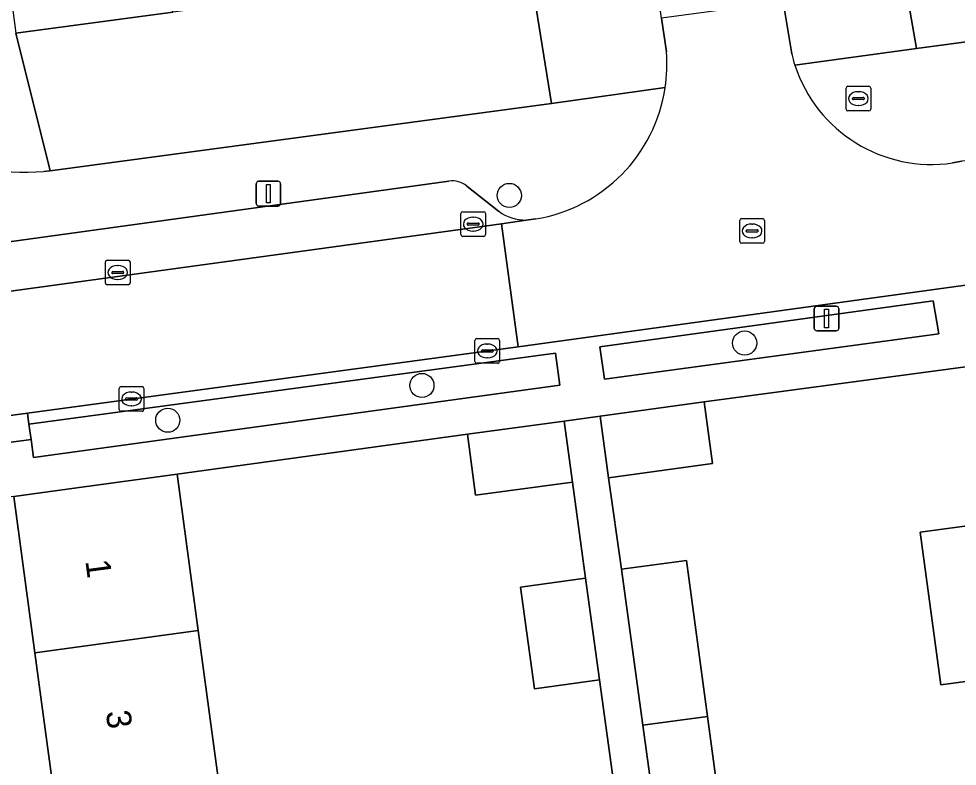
# Model space of a CAD drawing. Extents: x 159053 to 160042, y 380449 to 381423.
# Drawn here: x 159553.7 to 159591.74, y 380955.93 to 380986.2 of the extents above; entities that cross this region are included whole.
import ezdxf

# ---------------------------------------------------------------- set-up
doc = ezdxf.new("R2010")
doc.units = 0
for name, color, linetype in [('IMGEO_Boom', 7, 'Continuous'), ('IMGEO_Brandkraan', 7, 'Continuous'), ('IMGEO_Erf', 7, 'Continuous'), ('IMGEO_Groenvoorziening', 7, 'Continuous'), ('IMGEO_Kolk', 7, 'Continuous'), ('IMGEO_Lichtmast', 7, 'Continuous'), ('IMGEO_Muur', 7, 'Continuous'), ('IMGEO_Pand', 7, 'Continuous'), ('IMGEO_Pand_nummerreeks', 7, 'Continuous'), ('IMGEO_Parkeervlak_open', 7, 'Continuous'), ('IMGEO_Rijbaan_lokaal_open', 7, 'Continuous'), ('IMGEO_Rioolput', 7, 'Continuous'), ('IMGEO_Voetpad_op_trap', 7, 'Continuous'), ('IMGEO_Voetpad_open', 7, 'Continuous')]:
    doc.layers.add(name, color=color, linetype=linetype)

msp = doc.modelspace()

# ---------------------------------------------------------------- linework, layer by layer
at = {"layer": 'IMGEO_Boom'}
for centre in [(159573.584, 380979.049), (159583.121, 380973.071), (159570.042, 380971.353), (159559.743, 380969.946)]:
    msp.add_circle(centre, 0.489, dxfattribs=at)
at = {"layer": 'IMGEO_Brandkraan'}
for p, q in [((159587.23, 380982.545), (159587.23, 380983.397)), ((159587.305, 380983.471), (159588.157, 380983.471)), ((159587.718, 380983.251), (159587.743, 380983.251)), ((159588.231, 380983.397), (159588.231, 380982.545)), ((159587.489, 380982.965), (159587.489, 380982.977)), ((159587.927, 380982.928), (159587.529, 380982.928)), ((159587.532, 380983.014), (159587.93, 380983.014)), ((159587.973, 380982.977), (159587.973, 380982.965)), ((159588.157, 380982.471), (159587.305, 380982.471)), ((159587.741, 380982.691), (159587.716, 380982.691))]:
    msp.add_line(p, q, dxfattribs=at)
for points in [[(159587.23, 380982.545), (159587.23, 380983.397)], [(159587.305, 380983.471), (159588.157, 380983.471)], [(159588.231, 380983.397), (159588.231, 380982.545)], [(159588.157, 380982.471), (159587.305, 380982.471)]]:
    msp.add_lwpolyline(points, dxfattribs=at)
for centre, radius, start, end in [((159587.307, 380983.395), 0.0765, 91.552, 178.448), ((159587.307, 380983.395), 0.0765, 91.552, 178.448), ((159588.155, 380983.395), 0.0765, 1.552, 88.448), ((159588.155, 380983.395), 0.0765, 1.552, 88.448), ((159587.529, 380982.974), 0.0403, 85.8775, 175.7526), ((159587.526, 380982.964), 0.0366, 178.938, 274.7102), ((159587.93, 380982.971), 0.043, 264.8664, 352.4533), ((159587.934, 380982.976), 0.0386, 1.7309, 96.639), ((159587.307, 380982.547), 0.0765, 181.552, 268.448), ((159587.307, 380982.547), 0.0765, 181.552, 268.448), ((159588.155, 380982.547), 0.0765, 271.552, 358.448), ((159588.155, 380982.547), 0.0765, 271.552, 358.448)]:
    msp.add_arc(centre, radius, start, end, dxfattribs=at)
for centre, major_axis, ratio, start_param, end_param in [((159587.717, 380982.971), (-0.387, 0.002), 0.722429, 4.712389, 7.853982), ((159587.742, 380982.971), (-0.39, 0.002), 0.717154, 1.570796, 4.712389)]:
    msp.add_ellipse(centre, major_axis=major_axis, ratio=ratio, start_param=start_param, end_param=end_param, dxfattribs=at)
at = {"layer": 'IMGEO_Erf'}
msp.add_lwpolyline([(159629.325, 381012.778), (159620.225, 381011.443), (159619.631, 381015.49), (159606.715, 381013.595), (159606.672, 381013.887), (159603.856, 381013.811), (159603.9, 381013.367), (159601.077, 381012.94), (159595.844, 381012.15), (159595.511, 381014.617), (159594.439, 381014.46), (159594.956, 381010.935), (159586.122, 381009.639), (159587.893, 380997.568), (159590.084, 380985.004), (159632.613, 380990.715), (159631.088, 381000), (159630.309, 381005.645)], close=True, dxfattribs=at)
for points in [[(159552.695, 380992.276), (159559.053, 380993.13), (159565.262, 380993.963), (159566.666, 380994.152), (159571.621, 380994.818), (159572.515, 380988.162), (159566.157, 380987.308), (159559.948, 380986.474), (159553.589, 380985.62), (159554.983, 380980.049), (159575.287, 380982.768), (159574.532, 380987.48), (159573.254, 380997.153), (159571.578, 381009.42), (159563.123, 381008.171), (159562.595, 381011.752), (159561.106, 381011.532), (159561.428, 381009.12), (159556.975, 381008.526), (159553.35, 381008.042)], [(159593.088, 380972.249), (159581.476, 380970.686), (159581.814, 380968.189), (159577.607, 380967.619), (159578.129, 380963.91), (159580.762, 380964.266), (159581.616, 380957.945), (159582.173, 380953.826)], [(159577.808, 380955.319), (159577.242, 380959.429), (159574.599, 380959.064), (159574.032, 380963.18), (159576.675, 380963.544), (159576.138, 380967.442), (159572.22, 380966.911), (159571.886, 380969.384), (159560.123, 380967.756), (159560.979, 380961.426), (159561.815, 380955.248)], [(159594.782, 380959.727), (159591.065, 380959.224), (159590.229, 380965.41), (159593.945, 380965.913)]]:
    msp.add_lwpolyline(points, dxfattribs=at)
at = {"layer": 'IMGEO_Groenvoorziening'}
msp.add_lwpolyline([(159554.723, 380980.014), (159554.983, 380980.049), (159553.589, 380985.62)], dxfattribs=at)
for points in [[(159590.984, 380973.45), (159590.756, 380974.787), (159577.253, 380972.921), (159577.439, 380971.615)], [(159575.629, 380971.369), (159575.461, 380972.664), (159554.113, 380969.784), (159554.204, 380969.164), (159554.307, 380968.431)]]:
    msp.add_lwpolyline(points, close=True, dxfattribs=at)
msp.add_arc((159553.913, 380997.773), 17.777, 239.325, 272.6107, dxfattribs=at)
at = {"layer": 'IMGEO_Kolk'}
for p, q in [((159571.621, 380977.462), (159571.621, 380978.314)), ((159571.696, 380978.388), (159572.548, 380978.388)), ((159572.622, 380978.314), (159572.622, 380977.462)), ((159571.88, 380977.882), (159571.88, 380977.894)), ((159572.318, 380977.845), (159571.92, 380977.845)), ((159571.923, 380977.931), (159572.321, 380977.931)), ((159572.109, 380978.168), (159572.134, 380978.168)), ((159572.364, 380977.894), (159572.364, 380977.882)), ((159572.132, 380977.608), (159572.107, 380977.608)), ((159572.548, 380977.388), (159571.696, 380977.388)), ((159557.214, 380975.502), (159557.214, 380976.354)), ((159557.289, 380976.428), (159558.141, 380976.428)), ((159558.215, 380976.354), (159558.215, 380975.502)), ((159557.473, 380975.922), (159557.473, 380975.934)), ((159557.516, 380975.971), (159557.914, 380975.971)), ((159557.702, 380976.208), (159557.727, 380976.208)), ((159557.957, 380975.934), (159557.957, 380975.922)), ((159557.911, 380975.885), (159557.513, 380975.885)), ((159557.725, 380975.648), (159557.7, 380975.648)), ((159558.141, 380975.428), (159557.289, 380975.428)), ((159572.191, 380972.324), (159572.191, 380973.176)), ((159572.266, 380973.25), (159573.118, 380973.25)), ((159572.679, 380973.03), (159572.704, 380973.03)), ((159573.192, 380973.176), (159573.192, 380972.324)), ((159572.45, 380972.744), (159572.45, 380972.756)), ((159572.888, 380972.707), (159572.49, 380972.707)), ((159572.493, 380972.793), (159572.891, 380972.793)), ((159572.934, 380972.756), (159572.934, 380972.744)), ((159573.118, 380972.25), (159572.266, 380972.25)), ((159572.702, 380972.47), (159572.677, 380972.47)), ((159557.775, 380970.38), (159557.775, 380971.232)), ((159557.85, 380971.306), (159558.702, 380971.306)), ((159558.263, 380971.086), (159558.288, 380971.086)), ((159558.776, 380971.232), (159558.776, 380970.38)), ((159558.034, 380970.8), (159558.034, 380970.812)), ((159558.472, 380970.763), (159558.074, 380970.763)), ((159558.077, 380970.849), (159558.475, 380970.849)), ((159558.518, 380970.812), (159558.518, 380970.8)), ((159558.702, 380970.306), (159557.85, 380970.306)), ((159558.286, 380970.526), (159558.261, 380970.526))]:
    msp.add_line(p, q, dxfattribs=at)
for points in [[(159571.621, 380977.462), (159571.621, 380978.314)], [(159571.696, 380978.388), (159572.548, 380978.388)], [(159572.622, 380978.314), (159572.622, 380977.462)], [(159572.548, 380977.388), (159571.696, 380977.388)], [(159557.214, 380975.502), (159557.214, 380976.354)], [(159557.289, 380976.428), (159558.141, 380976.428)], [(159558.215, 380976.354), (159558.215, 380975.502)], [(159558.141, 380975.428), (159557.289, 380975.428)], [(159572.191, 380972.324), (159572.191, 380973.176)], [(159572.266, 380973.25), (159573.118, 380973.25)], [(159573.192, 380973.176), (159573.192, 380972.324)], [(159573.118, 380972.25), (159572.266, 380972.25)], [(159557.775, 380970.38), (159557.775, 380971.232)], [(159557.85, 380971.306), (159558.702, 380971.306)], [(159558.776, 380971.232), (159558.776, 380970.38)], [(159558.702, 380970.306), (159557.85, 380970.306)]]:
    msp.add_lwpolyline(points, dxfattribs=at)
for centre, radius, start, end in [((159571.698, 380978.312), 0.0765, 91.552, 178.448), ((159571.698, 380978.312), 0.0765, 91.552, 178.448), ((159572.546, 380978.312), 0.0765, 1.552, 88.448), ((159572.546, 380978.312), 0.0765, 1.552, 88.448), ((159571.92, 380977.891), 0.0403, 85.8775, 175.7526), ((159571.917, 380977.881), 0.0366, 178.938, 274.7102), ((159572.321, 380977.888), 0.043, 264.8664, 352.4533), ((159572.325, 380977.893), 0.0386, 1.7309, 96.639), ((159571.698, 380977.464), 0.0765, 181.552, 268.448), ((159571.698, 380977.464), 0.0765, 181.552, 268.448), ((159572.546, 380977.464), 0.0765, 271.552, 358.448), ((159572.546, 380977.464), 0.0765, 271.552, 358.448), ((159557.291, 380976.352), 0.0765, 91.552, 178.448), ((159557.291, 380976.352), 0.0765, 91.552, 178.448), ((159558.139, 380976.352), 0.0765, 1.552, 88.448), ((159558.139, 380976.352), 0.0765, 1.552, 88.448), ((159557.513, 380975.931), 0.0403, 85.8775, 175.7526), ((159557.918, 380975.933), 0.0386, 1.7309, 96.639), ((159557.51, 380975.921), 0.0366, 178.938, 274.7102), ((159557.914, 380975.928), 0.043, 264.8664, 352.4533), ((159557.291, 380975.504), 0.0765, 181.552, 268.448), ((159557.291, 380975.504), 0.0765, 181.552, 268.448), ((159558.139, 380975.504), 0.0765, 271.552, 358.448), ((159558.139, 380975.504), 0.0765, 271.552, 358.448), ((159572.268, 380973.174), 0.0765, 91.552, 178.448), ((159572.268, 380973.174), 0.0765, 91.552, 178.448), ((159573.116, 380973.174), 0.0765, 1.552, 88.448), ((159573.116, 380973.174), 0.0765, 1.552, 88.448), ((159572.49, 380972.753), 0.0403, 85.8775, 175.7526), ((159572.487, 380972.743), 0.0366, 178.938, 274.7102), ((159572.891, 380972.75), 0.043, 264.8664, 352.4533), ((159572.895, 380972.755), 0.0386, 1.7309, 96.639), ((159572.268, 380972.326), 0.0765, 181.552, 268.448), ((159572.268, 380972.326), 0.0765, 181.552, 268.448), ((159573.116, 380972.326), 0.0765, 271.552, 358.448), ((159573.116, 380972.326), 0.0765, 271.552, 358.448), ((159557.852, 380971.23), 0.0765, 91.552, 178.448), ((159557.852, 380971.23), 0.0765, 91.552, 178.448), ((159558.7, 380971.23), 0.0765, 1.552, 88.448), ((159558.7, 380971.23), 0.0765, 1.552, 88.448), ((159558.074, 380970.809), 0.0403, 85.8775, 175.7526), ((159558.071, 380970.799), 0.0366, 178.938, 274.7102), ((159558.475, 380970.806), 0.043, 264.8664, 352.4533), ((159558.479, 380970.811), 0.0386, 1.7309, 96.639), ((159557.852, 380970.382), 0.0765, 181.552, 268.448), ((159557.852, 380970.382), 0.0765, 181.552, 268.448), ((159558.7, 380970.382), 0.0765, 271.552, 358.448), ((159558.7, 380970.382), 0.0765, 271.552, 358.448)]:
    msp.add_arc(centre, radius, start, end, dxfattribs=at)
for centre, major_axis, ratio, start_param, end_param in [((159572.108, 380977.888), (-0.387, 0.002), 0.722429, 4.712389, 7.853982), ((159572.133, 380977.888), (-0.39, 0.002), 0.717154, 1.570796, 4.712389), ((159557.701, 380975.928), (-0.387, 0.002), 0.722429, 4.712389, 7.853982), ((159557.726, 380975.928), (-0.39, 0.002), 0.717154, 1.570796, 4.712389), ((159572.678, 380972.75), (-0.387, 0.002), 0.722429, 4.712389, 7.853982), ((159572.703, 380972.75), (-0.39, 0.002), 0.717154, 1.570796, 4.712389), ((159558.262, 380970.806), (-0.387, 0.002), 0.722429, 4.712389, 7.853982), ((159558.287, 380970.806), (-0.39, 0.002), 0.717154, 1.570796, 4.712389)]:
    msp.add_ellipse(centre, major_axis=major_axis, ratio=ratio, start_param=start_param, end_param=end_param, dxfattribs=at)
at = {"layer": 'IMGEO_Lichtmast'}
for p, q in [((159563.324, 380978.721), (159563.324, 380979.521)), ((159563.324, 380979.521), (159563.324, 380978.721)), ((159563.424, 380979.621), (159564.214, 380979.621)), ((159564.214, 380979.621), (159563.424, 380979.621)), ((159564.314, 380979.521), (159564.314, 380978.721)), ((159564.314, 380978.721), (159564.314, 380979.521)), ((159564.214, 380978.621), (159563.424, 380978.621)), ((159563.424, 380978.621), (159564.214, 380978.621)), ((159585.943, 380973.665), (159585.943, 380974.465)), ((159585.943, 380974.465), (159585.943, 380973.665)), ((159586.043, 380974.565), (159586.833, 380974.565)), ((159586.833, 380974.565), (159586.043, 380974.565)), ((159586.933, 380974.465), (159586.933, 380973.665)), ((159586.933, 380973.665), (159586.933, 380974.465)), ((159586.833, 380973.565), (159586.043, 380973.565)), ((159586.043, 380973.565), (159586.833, 380973.565))]:
    msp.add_line(p, q, dxfattribs=at)
for points in [[(159563.744, 380979.496), (159563.894, 380979.496), (159563.894, 380978.746), (159563.744, 380978.746), (159563.744, 380979.496)], [(159586.363, 380974.44), (159586.513, 380974.44), (159586.513, 380973.69), (159586.363, 380973.69), (159586.363, 380974.44)]]:
    msp.add_lwpolyline(points, dxfattribs=at)
for centre, start, end in [((159563.424, 380979.521), 90, 180), ((159563.424, 380979.521), 90, 180), ((159564.214, 380979.521), 0, 90), ((159564.214, 380979.521), 360, 90), ((159563.424, 380978.721), 180, 270), ((159563.424, 380978.721), 180, 270), ((159564.214, 380978.721), 270, 0), ((159564.214, 380978.721), 270, 0), ((159586.043, 380974.465), 90, 180), ((159586.043, 380974.465), 90, 180), ((159586.833, 380974.465), 0, 90), ((159586.833, 380974.465), 360, 90), ((159586.043, 380973.665), 180, 270), ((159586.043, 380973.665), 180, 270), ((159586.833, 380973.665), 270, 0), ((159586.833, 380973.665), 270, 0)]:
    msp.add_arc(centre, 0.1, start, end, dxfattribs=at)
at = {"layer": 'IMGEO_Muur'}
for points in [[(159581.476, 380970.686), (159593.088, 380972.249)], [(159560.123, 380967.756), (159571.886, 380969.384)]]:
    msp.add_lwpolyline(points, dxfattribs=at)
at = {"layer": 'IMGEO_Pand'}
for points in [[(159559.053, 380993.13), (159552.695, 380992.276), (159552.923, 380990.576), (159553.589, 380985.62), (159559.948, 380986.474)], [(159577.269, 380970.116), (159577.607, 380967.619), (159581.814, 380968.189), (159581.476, 380970.686)], [(159576.138, 380967.442), (159575.804, 380969.914), (159571.886, 380969.384), (159572.22, 380966.911)], [(159560.979, 380961.426), (159560.123, 380967.756), (159556.064, 380967.207), (159553.503, 380966.86), (159554.36, 380960.526)], [(159601.433, 380960.627), (159600.596, 380966.812), (159593.945, 380965.913), (159590.229, 380965.41), (159591.065, 380959.224), (159594.782, 380959.727)], [(159578.129, 380963.91), (159578.991, 380957.59), (159581.616, 380957.945), (159580.762, 380964.266)], [(159576.675, 380963.544), (159574.032, 380963.18), (159574.599, 380959.064), (159577.242, 380959.429)], [(159555.196, 380954.348), (159561.815, 380955.248), (159560.979, 380961.426), (159554.36, 380960.526)], [(159581.616, 380957.945), (159578.991, 380957.59), (159579.56, 380953.465), (159582.173, 380953.826)]]:
    msp.add_lwpolyline(points, close=True, dxfattribs=at)
at = {"layer": 'IMGEO_Parkeervlak_open'}
for points in [[(159571.136, 380979.631), (159548.207, 380976.467)], [(159573.152, 380978.406), (159571.868, 380979.43)], [(159545.388, 380974.074), (159573.269, 380977.897), (159574.265, 380978.052)]]:
    msp.add_lwpolyline(points, dxfattribs=at)
for centre, radius, start, end in [((159571.265, 380978.667), 0.972, 51.6697, 97.6215), ((159574.242, 380979.905), 1.853, 233.9903, 270.7222)]:
    msp.add_arc(centre, radius, start, end, dxfattribs=at)
at = {"layer": 'IMGEO_Rijbaan_lokaal_open'}
for points in [[(159585.027, 380984.781), (159584.681, 380986.896), (159579.757, 380986.225), (159579.948, 380984.858)], [(159574.652, 380978.096), (159574.265, 380978.052), (159573.269, 380977.897), (159573.94, 380972.918), (159593.547, 380975.614), (159592.902, 380980.536), (159591.927, 380980.432), (159591.549, 380980.369)]]:
    msp.add_lwpolyline(points, dxfattribs=at)
msp.add_lwpolyline([(159573.269, 380977.897), (159545.388, 380974.074), (159546.141, 380969.164), (159554.06, 380970.237), (159573.94, 380972.918)], close=True, dxfattribs=at)
for centre, radius, start, end in [((159573.708, 380984.35), 6.261, 351.4471, 4.6524), ((159590.398, 380986.043), 5.518, 193.2197, 198.1394), ((159590.691, 380986.127), 5.822, 198.0332, 278.4762), ((159573.631, 380984.35), 6.337, 279.2722, 351.5518)]:
    msp.add_arc(centre, radius, start, end, dxfattribs=at)
at = {"layer": 'IMGEO_Rioolput'}
for p, q in [((159582.921, 380977.184), (159582.921, 380978.036)), ((159582.996, 380978.11), (159583.848, 380978.11)), ((159583.409, 380977.89), (159583.434, 380977.89)), ((159583.922, 380978.036), (159583.922, 380977.184)), ((159583.18, 380977.604), (159583.18, 380977.616)), ((159583.618, 380977.567), (159583.22, 380977.567)), ((159583.223, 380977.653), (159583.621, 380977.653)), ((159583.664, 380977.616), (159583.664, 380977.604)), ((159583.848, 380977.11), (159582.996, 380977.11)), ((159583.432, 380977.33), (159583.407, 380977.33))]:
    msp.add_line(p, q, dxfattribs=at)
for points in [[(159582.921, 380977.184), (159582.921, 380978.036)], [(159582.996, 380978.11), (159583.848, 380978.11)], [(159583.922, 380978.036), (159583.922, 380977.184)], [(159583.848, 380977.11), (159582.996, 380977.11)]]:
    msp.add_lwpolyline(points, dxfattribs=at)
for centre, radius, start, end in [((159582.998, 380978.034), 0.0765, 91.552, 178.448), ((159582.998, 380978.034), 0.0765, 91.552, 178.448), ((159583.846, 380978.034), 0.0765, 1.552, 88.448), ((159583.846, 380978.034), 0.0765, 1.552, 88.448), ((159583.22, 380977.613), 0.0403, 85.8775, 175.7526), ((159583.217, 380977.603), 0.0366, 178.938, 274.7102), ((159583.621, 380977.61), 0.043, 264.8664, 352.4533), ((159583.625, 380977.615), 0.0386, 1.7309, 96.639), ((159582.998, 380977.186), 0.0765, 181.552, 268.448), ((159582.998, 380977.186), 0.0765, 181.552, 268.448), ((159583.846, 380977.186), 0.0765, 271.552, 358.448), ((159583.846, 380977.186), 0.0765, 271.552, 358.448)]:
    msp.add_arc(centre, radius, start, end, dxfattribs=at)
for centre, major_axis, ratio, start_param, end_param in [((159583.408, 380977.61), (-0.387, 0.002), 0.722429, 4.712389, 7.853982), ((159583.433, 380977.61), (-0.39, 0.002), 0.717154, 1.570796, 4.712389)]:
    msp.add_ellipse(centre, major_axis=major_axis, ratio=ratio, start_param=start_param, end_param=end_param, dxfattribs=at)
at = {"layer": 'IMGEO_Voetpad_op_trap'}
for points in [[(159555.835, 381168.884), (159556.672, 381169.986), (159550.971, 381169.356), (159554.244, 381116.384), (159554.494, 381111.677), (159556.453, 381111.966), (159557.841, 381112.195), (159572.181, 381015.08), (159570.79, 381014.875), (159570.994, 381013.371), (159571.578, 381009.42), (159573.254, 380997.153), (159574.532, 380987.48), (159575.287, 380982.768), (159579.899, 380983.419)], [(159579.948, 380984.858), (159579.757, 380986.225), (159578.999, 380991.426)], [(159636.867, 380991.237), (159632.613, 380990.715), (159590.084, 380985.004), (159585.155, 380984.325)], [(159591.549, 380980.369), (159591.927, 380980.432)], [(159593.547, 380975.614), (159573.94, 380972.918), (159554.06, 380970.237), (159554.113, 380969.784), (159575.461, 380972.664), (159575.629, 380971.369), (159554.307, 380968.431), (159554.204, 380969.164), (159546.217, 380968.102)], [(159553.503, 380966.86), (159556.064, 380967.207), (159560.123, 380967.756), (159571.886, 380969.384), (159575.804, 380969.914), (159577.269, 380970.116), (159581.476, 380970.686), (159593.088, 380972.249), (159599.739, 380973.149), (159599.766, 380972.953), (159601.418, 380973.158), (159604.872, 380973.622), (159607.369, 380973.933)]]:
    msp.add_lwpolyline(points, dxfattribs=at)
for points in [[(159577.439, 380971.615), (159577.253, 380972.921), (159590.756, 380974.787), (159590.984, 380973.45)], [(159554.204, 380969.164), (159554.113, 380969.784), (159554.06, 380970.237), (159546.141, 380969.164), (159546.217, 380968.102)]]:
    msp.add_lwpolyline(points, close=True, dxfattribs=at)
for centre, radius, start, end in [((159573.708, 380984.35), 6.261, 351.4471, 4.6524), ((159590.691, 380986.127), 5.822, 198.0332, 278.4762)]:
    msp.add_arc(centre, radius, start, end, dxfattribs=at)
at = {"layer": 'IMGEO_Voetpad_open'}
for points in [[(159585.155, 380984.325), (159590.084, 380985.004), (159587.893, 380997.568), (159586.122, 381009.639), (159585.534, 381013.648), (159585.319, 381015.173), (159583.892, 381014.966), (159567.971, 381123.474), (159567.796, 381126.635), (159565.061, 381170.206)], [(159565.779, 381116.931), (159567.081, 381108.31), (159571.387, 381078.814), (159571.803, 381076), (159572.215, 381073.211), (159577.073, 381040.334), (159582.77, 381001.343), (159582.966, 381000), (159583.146, 380998.609), (159584.187, 380990.361), (159584.681, 380986.896), (159585.027, 380984.781)], [(159579.899, 380983.419), (159575.287, 380982.768), (159554.983, 380980.049), (159554.723, 380980.014)], [(159548.207, 380976.467), (159571.136, 380979.631)], [(159571.868, 380979.43), (159573.152, 380978.406)], [(159574.265, 380978.052), (159574.652, 380978.096)]]:
    msp.add_lwpolyline(points, dxfattribs=at)
for points in [[(159579.56, 380953.465), (159578.991, 380957.59), (159578.129, 380963.91), (159577.607, 380967.619), (159577.269, 380970.116), (159575.804, 380969.914), (159576.138, 380967.442), (159576.675, 380963.544), (159577.242, 380959.429), (159577.808, 380955.319), (159578.374, 380951.207), (159578.951, 380947.02), (159579.493, 380943.088), (159580.076, 380938.853), (159580.497, 380935.796), (159581.968, 380935.998), (159581.855, 380936.832), (159580.962, 380943.302), (159580.697, 380945.224), (159579.884, 380951.119)], [(159557.704, 380935.811), (159556.868, 380941.99), (159556.032, 380948.169), (159555.196, 380954.348), (159554.36, 380960.526), (159553.503, 380966.86), (159551.678, 380966.63), (159551.745, 380966.134), (159557.786, 380921.412), (159559.619, 380921.66), (159559.396, 380923.307), (159558.54, 380929.633)]]:
    msp.add_lwpolyline(points, close=True, dxfattribs=at)
for centre, radius, start, end in [((159590.398, 380986.043), 5.518, 193.2197, 198.1394), ((159573.631, 380984.35), 6.337, 279.2722, 351.5518), ((159553.913, 380997.773), 17.777, 239.325, 272.6107), ((159571.265, 380978.667), 0.972, 51.6697, 97.6215), ((159574.242, 380979.905), 1.853, 233.9903, 270.7222)]:
    msp.add_arc(centre, radius, start, end, dxfattribs=at)

# ---------------------------------------------------------------- texts
at = {"layer": 'IMGEO_Pand_nummerreeks'}
for s, p in [('1', (159556.4, 380964.247)), ('3', (159557.227, 380958.138))]:
    msp.add_text(s, height=1, rotation=277.7057, dxfattribs=at).set_placement(p)

doc.saveas('drawing.dxf')
